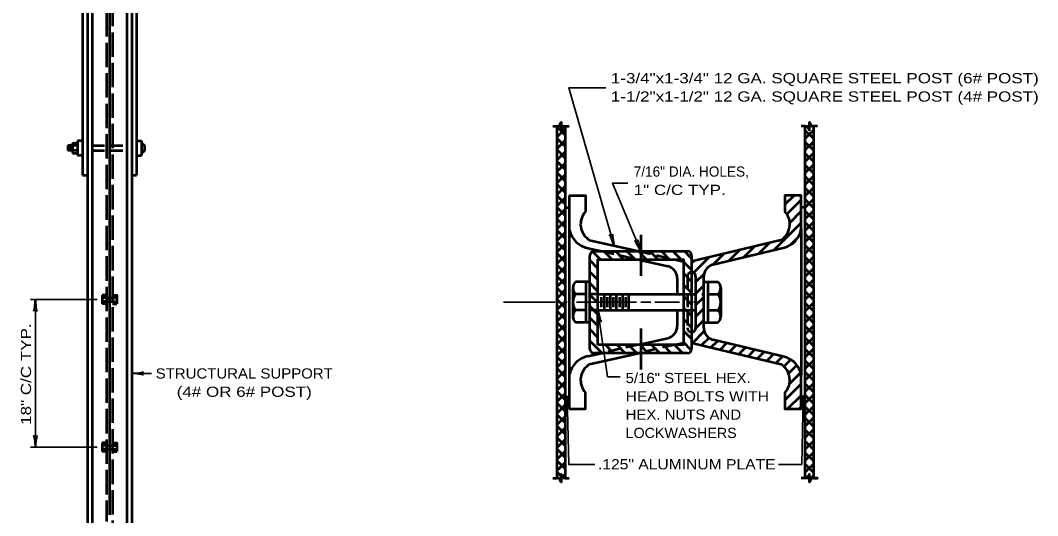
# Model space of a CAD drawing. Extents: x -54 to 626, y -369 to 71.
# Drawn here: x 180.3 to 430.3, y -222.5 to -100.7 of the extents above; entities that cross this region are included whole.
import ezdxf
from ezdxf.enums import TextEntityAlignment as Align

# ---------------------------------------------------------------- set-up
doc = ezdxf.new("R2010")
doc.units = 0
doc.linetypes.add('LONG_DASHED', pattern=[7.5, 6, -1.5])
doc.linetypes.add('MEDIUM_DASHED', pattern=[4.5, 3, -1.5])
doc.layers.add('1', color=7, linetype='Continuous', lineweight=53)

msp = doc.modelspace()

# ---------------------------------------------------------------- linework, layer by layer
at = {"layer": '1'}
for p, q in [((197.973, -26.265), (197.973, -228.335)), ((202.208, -26.265), (202.208, -222.285)), ((195.553, -28.685), (195.553, -138.795)), ((196.763, -28.685), (196.763, -228.335)), ((206.443, -28.685), (206.443, -228.335)), ((207.653, -28.685), (207.653, -228.335)), ((208.863, -28.685), (208.863, -138.795)), ((311.19, -126.746), (312.19, -126.746)), ((314.19, -128.931), (312.19, -126.931)), ((312.19, -129.378), (314.19, -127.378)), ((314.19, -126.746), (315.19, -126.746)), ((373.19, -126.746), (372.19, -126.746)), ((373.19, -126.917), (373.36, -126.746)), ((374.19, -125.917), (374.246, -125.86)), ((374.425, -126.218), (374.19, -125.982)), ((375.19, -126.982), (374.954, -126.746)), ((376.19, -126.746), (375.19, -126.746)), ((314.19, -131.759), (312.19, -129.759)), ((373.19, -129.745), (375.19, -127.745)), ((375.19, -129.811), (373.19, -127.811)), ((194.343, -131.535), (191.923, -131.535)), ((191.923, -131.535), (191.923, -132.745)), ((192.528, -131.838), (192.528, -132.443)), ((193.133, -130.93), (193.133, -133.35)), ((193.133, -130.93), (194.343, -130.93)), ((195.553, -130.325), (194.343, -130.325)), ((194.343, -130.325), (194.343, -133.955)), ((208.863, -130.325), (210.073, -130.325)), ((210.073, -130.325), (210.073, -133.955)), ((312.19, -132.207), (314.19, -130.207)), ((373.19, -132.573), (375.19, -130.573)), ((375.19, -132.639), (373.19, -130.639)), ((194.343, -132.745), (191.923, -132.745)), ((193.133, -133.35), (194.343, -133.35)), ((195.553, -133.955), (194.343, -133.955)), ((208.863, -133.955), (210.073, -133.955)), ((314.19, -134.588), (312.19, -132.588)), ((312.19, -135.035), (314.19, -133.035)), ((373.19, -135.402), (375.19, -133.402)), ((375.19, -135.467), (373.19, -133.467)), ((314.19, -137.416), (312.19, -135.416)), ((312.19, -137.863), (314.19, -135.863)), ((373.19, -138.23), (375.19, -136.23)), ((375.19, -138.296), (373.19, -136.296)), ((195.553, -138.795), (196.763, -138.795)), ((207.653, -138.795), (208.863, -138.795)), ((314.19, -140.245), (312.19, -138.245)), ((312.19, -140.692), (314.19, -138.692)), ((373.19, -141.059), (375.19, -139.059)), ((375.19, -141.124), (373.19, -139.124)), ((314.19, -143.073), (312.19, -141.073)), ((312.19, -143.52), (314.19, -141.52)), ((373.19, -143.887), (375.19, -141.887)), ((375.19, -143.953), (373.19, -141.953)), ((314.19, -145.901), (312.19, -143.901)), ((312.19, -146.349), (314.19, -144.349)), ((315.19, -143.746), (315.19, -196.246)), ((368.19, -145.99), (370.433, -143.746)), ((368.654, -148.354), (372.19, -144.818)), ((373.19, -146.716), (375.19, -144.716)), ((375.19, -146.781), (373.19, -144.781)), ((314.19, -148.73), (312.19, -146.73)), ((312.19, -149.177), (314.19, -147.177)), ((314.19, -146.746), (315.19, -146.746)), ((373.19, -146.746), (372.19, -146.746)), ((314.19, -151.558), (312.19, -149.558)), ((312.19, -152.006), (314.19, -150.006)), ((369.366, -150.471), (372.19, -147.647)), ((373.19, -149.544), (375.19, -147.544)), ((375.19, -149.61), (373.19, -147.61)), ((314.19, -154.387), (312.19, -152.387)), ((365.445, -157.219), (372.19, -150.475)), ((372.19, -152.045), (372.19, -187.948)), ((373.19, -152.372), (375.19, -150.372)), ((375.19, -152.438), (373.19, -150.438)), ((312.19, -154.834), (314.19, -152.834)), ((320.19, -154.746), (332.247, -157.487)), ((332.746, -153.487), (332.746, -163.487)), ((369.593, -155.9), (371.362, -154.131)), ((373.19, -155.201), (375.19, -153.201)), ((375.19, -155.266), (373.19, -153.266)), ((314.19, -157.215), (312.19, -155.215)), ((312.19, -157.662), (314.19, -155.662)), ((319.746, -156.697), (323.222, -157.487)), ((321.246, -157.487), (344.246, -157.487)), ((325.707, -159.487), (323.707, -157.487)), ((328.535, -159.487), (326.535, -157.487)), ((331.364, -159.487), (329.364, -157.487)), ((334.192, -159.487), (332.192, -157.487)), ((337.021, -159.487), (335.021, -157.487)), ((339.849, -159.487), (337.849, -157.487)), ((342.678, -159.487), (340.678, -157.487)), ((345.246, -159.227), (343.506, -157.487)), ((350.55, -160.776), (368.089, -156.588)), ((354.298, -159.881), (357, -157.18)), ((358.014, -158.994), (360.715, -156.293)), ((361.73, -158.107), (364.431, -155.405)), ((373.19, -158.029), (375.19, -156.029)), ((375.19, -158.095), (373.19, -156.095)), ((314.19, -160.044), (312.19, -158.044)), ((312.19, -160.491), (314.19, -158.491)), ((320.246, -181.506), (320.246, -158.487)), ((322.246, -161.683), (320.246, -159.683)), ((322.879, -159.487), (320.936, -157.544)), ((332.022, -159.487), (339.411, -161.166)), ((341.046, -159.487), (343.246, -159.987)), ((345.246, -158.487), (345.246, -159.987)), ((345.246, -160.448), (345.852, -159.842)), ((345.751, -162.771), (349.568, -158.955)), ((350.582, -160.769), (353.284, -158.067)), ((373.19, -160.858), (375.19, -158.858)), ((375.19, -160.923), (373.19, -158.923)), ((314.19, -162.872), (312.19, -160.872)), ((312.19, -163.319), (314.19, -161.319)), ((322.246, -164.511), (320.246, -162.511)), ((345.246, -162.056), (343.246, -160.056)), ((373.19, -163.686), (375.19, -161.686)), ((375.19, -163.752), (373.19, -161.752)), ((314.19, -165.7), (312.19, -163.7)), ((312.19, -166.148), (314.19, -164.148)), ((320.246, -164.996), (316.746, -164.996)), ((319.246, -164.996), (319.246, -174.996)), ((341.746, -164.091), (341.746, -167.996)), ((345.246, -164.884), (343.246, -162.884)), ((345.246, -162.612), (345.246, -177.381)), ((346.246, -165.105), (348.324, -163.027)), ((346.246, -163.694), (346.246, -176.299)), ((348.246, -176.299), (348.246, -163.694)), ((348.246, -164.996), (351.746, -164.996)), ((349.246, -164.996), (349.246, -174.996)), ((373.19, -166.515), (375.19, -164.515)), ((375.19, -166.58), (373.19, -164.58)), ((314.19, -168.529), (312.19, -166.529)), ((312.19, -168.976), (314.19, -166.976)), ((316.074, -166.502), (316.074, -173.491)), ((322.246, -167.34), (320.246, -165.34)), ((345.246, -167.712), (343.246, -165.712)), ((346.246, -167.933), (348.246, -165.933)), ((352.419, -166.502), (352.419, -173.491)), ((373.19, -169.343), (375.19, -167.343)), ((375.19, -169.409), (373.19, -167.409)), ((200.393, -168.289), (200.393, -170.407)), ((201.451, -168.289), (200.393, -168.289)), ((314.19, -171.357), (312.19, -169.357)), ((312.19, -171.805), (314.19, -169.805)), ((319.246, -167.996), (316.746, -167.996)), ((322.246, -170.168), (320.246, -168.168)), ((322.246, -167.996), (343.246, -167.996)), ((322.996, -168.746), (322.996, -171.246)), ((323.746, -167.996), (323.746, -171.996)), ((324.496, -168.746), (324.496, -171.246)), ((325.246, -167.996), (325.246, -171.996)), ((325.996, -168.746), (325.996, -171.246)), ((326.746, -167.996), (326.746, -171.996)), ((327.496, -168.746), (327.496, -171.246)), ((328.246, -167.996), (328.246, -171.996)), ((328.996, -168.746), (328.996, -171.246)), ((329.746, -167.996), (329.746, -171.996)), ((345.246, -170.541), (343.246, -168.541)), ((346.246, -170.761), (348.246, -168.761)), ((349.246, -167.996), (351.746, -167.996)), ((201.451, -170.407), (200.393, -170.407)), ((202.964, -170.407), (204.023, -170.407)), ((314.19, -174.186), (312.19, -172.186)), ((319.246, -171.996), (316.746, -171.996)), ((322.246, -172.997), (320.246, -170.997)), ((322.246, -171.996), (343.246, -171.996)), ((341.746, -171.996), (341.746, -175.902)), ((345.246, -173.369), (343.246, -171.369)), ((346.246, -173.59), (348.246, -171.59)), ((349.246, -171.996), (351.746, -171.996)), ((373.19, -172.171), (375.19, -170.171)), ((375.19, -172.237), (373.19, -170.237)), ((312.19, -174.633), (314.19, -172.633)), ((314.19, -177.014), (312.19, -175.014)), ((320.246, -174.996), (316.746, -174.996)), ((322.246, -175.825), (320.246, -173.825)), ((345.246, -176.198), (343.246, -174.198)), ((346.229, -176.436), (348.246, -174.418)), ((348.246, -174.996), (351.746, -174.996)), ((373.19, -175), (375.19, -173)), ((375.19, -175.065), (373.19, -173.065)), ((312.19, -177.461), (314.19, -175.461)), ((322.246, -178.654), (320.246, -176.654)), ((332.746, -176.506), (332.746, -186.506)), ((345.246, -179.026), (343.246, -177.026)), ((345.246, -177.418), (345.284, -177.38)), ((345.44, -180.053), (348.38, -177.114)), ((373.19, -177.828), (375.19, -175.828)), ((375.19, -177.894), (373.19, -175.894)), ((314.19, -179.843), (312.19, -177.843)), ((312.19, -180.29), (314.19, -178.29)), ((323.271, -182.506), (320.246, -179.482)), ((332.022, -180.506), (339.411, -178.827)), ((341.046, -180.506), (343.246, -180.006)), ((345.188, -181.796), (343.246, -179.855)), ((345.246, -180.006), (345.246, -181.506)), ((347.724, -180.598), (349.563, -178.758)), ((350.007, -181.143), (351.667, -179.483)), ((368.089, -183.405), (350.55, -179.216)), ((373.19, -180.657), (375.19, -178.657)), ((375.19, -180.722), (373.19, -178.722)), ((314.19, -182.671), (312.19, -180.671)), ((312.19, -183.118), (314.19, -181.118)), ((319.746, -183.296), (323.222, -182.506)), ((320.19, -185.246), (332.246, -182.506)), ((344.246, -182.506), (321.246, -182.506)), ((326.099, -182.506), (324.099, -180.506)), ((328.928, -182.506), (326.928, -180.506)), ((331.756, -182.506), (329.756, -180.506)), ((334.585, -182.506), (332.585, -180.506)), ((337.413, -182.506), (335.413, -180.506)), ((340.241, -182.506), (338.241, -180.506)), ((343.07, -182.506), (341.07, -180.506)), ((352.29, -181.688), (353.95, -180.029)), ((354.573, -182.234), (356.233, -180.574)), ((356.856, -182.779), (358.516, -181.119)), ((359.14, -183.324), (360.8, -181.664)), ((361.423, -183.869), (363.083, -182.209)), ((373.19, -183.485), (375.19, -181.485)), ((375.19, -183.551), (373.19, -181.551)), ((314.19, -185.499), (312.19, -183.499)), ((312.19, -185.947), (314.19, -183.947)), ((363.706, -184.415), (365.366, -182.755)), ((365.989, -184.96), (367.649, -183.3)), ((367.948, -185.829), (369.656, -184.121)), ((373.19, -186.314), (375.19, -184.314)), ((375.19, -186.379), (373.19, -184.379)), ((314.19, -188.328), (312.19, -186.328)), ((312.19, -188.775), (314.19, -186.775)), ((369.079, -187.527), (371.114, -185.492)), ((369.269, -190.165), (372.044, -187.391)), ((373.19, -189.142), (375.19, -187.142)), ((375.19, -189.207), (373.19, -187.207)), ((314.19, -191.156), (312.19, -189.156)), ((312.19, -191.604), (314.19, -189.604)), ((373.19, -191.97), (375.19, -189.97)), ((314.19, -193.985), (312.19, -191.985)), ((312.19, -194.432), (314.19, -192.432)), ((368.19, -194.073), (372.19, -190.073)), ((375.19, -192.036), (373.19, -190.036)), ((314.19, -196.813), (312.19, -194.813)), ((314.19, -193.246), (315.19, -193.246)), ((368.845, -196.246), (372.19, -192.901)), ((373.19, -193.246), (372.19, -193.246)), ((373.19, -194.799), (375.19, -192.799)), ((375.19, -194.864), (373.19, -192.864)), ((312.19, -197.26), (314.19, -195.26)), ((371.673, -196.246), (372.19, -195.73)), ((373.19, -197.627), (375.19, -195.627)), ((375.19, -197.693), (373.19, -195.693)), ((314.19, -199.642), (312.19, -197.642)), ((312.19, -200.089), (314.19, -198.089)), ((373.19, -200.456), (375.19, -198.456)), ((375.19, -200.521), (373.19, -198.521)), ((314.19, -202.47), (312.19, -200.47)), ((312.19, -202.917), (314.19, -200.917)), ((373.19, -203.284), (375.19, -201.284)), ((375.19, -203.35), (373.19, -201.35)), ((200.393, -204.589), (200.393, -206.707)), ((201.451, -204.589), (200.393, -204.589)), ((314.19, -205.298), (312.19, -203.298)), ((312.19, -205.746), (314.19, -203.746)), ((373.19, -206.113), (375.19, -204.113)), ((375.19, -206.178), (373.19, -204.178)), ((201.451, -206.707), (200.393, -206.707)), ((202.964, -206.707), (204.023, -206.707)), ((314.19, -208.127), (312.19, -206.127)), ((312.19, -208.574), (314.19, -206.574)), ((373.19, -208.941), (375.19, -206.941)), ((375.19, -209.006), (373.19, -207.006)), ((314.19, -210.955), (312.19, -208.955)), ((312.19, -211.403), (314.19, -209.403)), ((373.19, -211.769), (375.19, -209.769)), ((375.19, -211.835), (373.19, -209.835)), ((313.19, -212.784), (312.19, -211.784)), ((313.518, -212.903), (314.19, -212.231)), ((311.19, -213.246), (312.19, -213.246)), ((312.851, -213.57), (313.19, -213.231)), ((314.19, -213.246), (315.19, -213.246)), ((373.19, -213.246), (372.19, -213.246)), ((373.773, -213.246), (373.19, -212.663)), ((374.541, -213.246), (375.19, -212.598))]:
    msp.add_line(p, q, dxfattribs=at)
at = {"layer": '1', "linetype": 'LONG_DASHED'}
for p, q in [((202.964, -28.685), (202.964, -228.335)), ((201.451, -46.23), (201.451, -223.926))]:
    msp.add_line(p, q, dxfattribs=at)
at = {"layer": '1', "linetype": 'MEDIUM_DASHED'}
for p, q in [((197.973, -131.535), (206.443, -131.535)), ((197.973, -132.745), (206.443, -132.745)), ((323.222, -157.487), (332.022, -159.487)), ((332.247, -157.487), (341.046, -159.487)), ((344.246, -163.694), (344.246, -176.299)), ((201.451, -168.894), (200.393, -168.894)), ((201.451, -169.802), (200.393, -169.802)), ((201.451, -168.894), (202.964, -168.894)), ((201.451, -168.894), (202.964, -168.894)), ((201.451, -169.802), (202.964, -169.802)), ((202.964, -168.894), (204.023, -168.894)), ((202.964, -169.802), (204.023, -169.802)), ((322.246, -167.996), (320.246, -167.996)), ((343.246, -167.996), (348.246, -167.996)), ((322.246, -171.996), (320.246, -171.996)), ((343.246, -171.996), (348.246, -171.996)), ((332.022, -180.506), (323.222, -182.506)), ((341.046, -180.506), (332.246, -182.506)), ((201.451, -205.194), (200.393, -205.194)), ((201.451, -206.102), (200.393, -206.102)), ((201.451, -205.194), (202.964, -205.194)), ((201.451, -206.102), (202.964, -206.102)), ((202.964, -205.194), (204.023, -205.194)), ((202.964, -206.102), (204.023, -206.102))]:
    msp.add_line(p, q, dxfattribs=at)
at = {"layer": '1', "lineweight": 35}
for p, q in [((199.183, -169.348), (182.771, -169.348)), ((183.981, -169.348), (183.981, -205.648)), ((299.017, -169.996), (311.69, -169.996)), ((313.69, -169.996), (314.69, -169.996)), ((316.984, -169.996), (331.746, -169.996)), ((332.746, -169.996), (335.246, -169.996)), ((336.246, -169.996), (342.246, -169.996)), ((345.71, -169.996), (347.198, -169.996)), ((207.653, -187.498), (212.493, -187.498)), ((314.69, -193.246), (315.059, -209.89)), ((372.69, -193.246), (372.321, -209.89)), ((199.183, -205.648), (182.771, -205.648)), ((315.014, -209.861), (321.49, -209.861)), ((366.651, -209.89), (372.365, -209.89))]:
    msp.add_line(p, q, dxfattribs=at)
for points in [[(326.218, -156.117), (315.102, -117.3), (324.167, -117.3)], [(332.746, -157.487), (325.846, -140.726), (329.606, -140.726)], [(322.246, -171.996), (324.623, -188.341), (327.713, -188.341)]]:
    msp.add_lwpolyline(points, dxfattribs=at)
at = {"layer": '1'}
for points in [[(312.19, -213.246), (312.19, -126.746), (312.69, -126.746), (313.19, -125.746), (313.19, -127.746), (313.69, -126.746), (314.19, -126.746), (314.19, -213.246), (313.69, -213.246), (313.19, -212.246), (313.19, -214.246), (312.69, -213.246)], [(373.19, -213.246), (373.19, -126.746), (373.69, -126.746), (374.19, -127.746), (374.19, -125.746), (374.69, -126.746), (375.19, -126.746), (375.19, -213.246), (376.19, -213.246)], [(373.19, -213.246), (373.19, -126.746), (373.69, -126.746), (374.19, -127.746), (374.19, -125.746), (374.69, -126.746), (375.19, -126.746), (375.19, -213.246), (374.69, -213.246), (374.19, -214.246), (374.19, -212.246), (373.69, -213.246)], [(322.246, -180.506), (322.246, -159.487), (343.246, -159.487), (343.246, -180.506)]]:
    msp.add_lwpolyline(points, close=True, dxfattribs=at)
for points in [[(315.19, -143.746), (319.19, -143.746), (319.19, -147.746)], [(372.19, -152.045), (372.19, -143.746), (368.19, -143.746), (368.19, -147.746)], [(367.19, -154.746), (345.246, -159.987), (345.246, -162.612)], [(202.964, -168.289), (204.023, -168.289), (204.023, -170.407)], [(345.246, -177.381), (345.246, -180.006), (367.19, -185.246)], [(368.19, -192.246), (368.19, -196.246), (372.19, -196.246), (372.19, -187.948)], [(315.19, -196.246), (319.19, -196.246), (319.19, -192.246)], [(202.964, -204.589), (204.023, -204.589), (204.023, -206.707)]]:
    msp.add_lwpolyline(points, dxfattribs=at)
for centre, radius, start, end in [((209.6, -132.14), 1.299, 291.34576, 68.65425), ((322.536, -150.84), 4.557, 137.24693, 239.01328), ((364.844, -150.84), 4.557, 300.98672, 42.75307), ((320.851, -151.057), 5.747, 192.24961, 258.91782), ((366.528, -151.057), 5.747, 285.76159, 350.09896), ((321.246, -158.487), 1, 90, 180), ((344.246, -158.487), 1, 0, 90), ((338.746, -164.091), 3, 0, 77.19552), ((351.246, -163.694), 3, 103.43049, 180), ((318.082, -166.496), 2.008, 131.68177, 180.15453), ((345.238, -163.623), 1.011, 355.93658, 88.42125), ((350.411, -166.496), 2.008, 359.84547, 48.31823), ((318.082, -166.496), 2.008, 180.15453, 228.31823), ((318.082, -166.507), 2.008, 179.84547, 228.31823), ((350.411, -166.496), 2.008, 311.68177, 359.84548), ((350.411, -166.507), 2.008, 311.68177, 0.15452), ((319.383, -169.996), 3.309, 142.81241, 217.18759), ((319.383, -169.996), 3.309, 142.81241, 217.18759), ((349.11, -169.996), 3.309, 322.81241, 37.18759), ((349.11, -169.996), 3.309, 322.81241, 37.18759), ((318.082, -173.486), 2.008, 131.68177, 180.15453), ((318.082, -173.496), 2.008, 131.68177, 179.84548), ((350.411, -173.486), 2.008, 359.84547, 48.31823), ((350.411, -173.496), 2.008, 0.15452, 48.31823), ((318.082, -173.496), 2.008, 179.84547, 228.31823), ((350.411, -173.496), 2.008, 311.68177, 0.15452), ((338.746, -175.902), 3, 282.80434, 0), ((345.238, -176.37), 1.011, 271.57875, 4.06342), ((351.246, -176.299), 3, 180, 256.56931), ((321.246, -181.506), 1, 180, 270), ((344.246, -181.506), 1, 270, 0), ((320.851, -188.936), 5.747, 101.08218, 167.75039), ((366.528, -188.936), 5.747, 9.90104, 74.23791), ((322.536, -189.153), 4.557, 120.98672, 222.75307), ((364.844, -189.153), 4.557, 317.24693, 59.01328)]:
    msp.add_arc(centre, radius, start, end, dxfattribs=at)
at = {"layer": '1', "linetype": 'MEDIUM_DASHED'}
for centre, start, end in [((345.255, -163.623), 91.57875, 184.06342), ((345.255, -176.37), 175.93658, 268.42125)]:
    msp.add_arc(centre, 1.011, start, end, dxfattribs=at)
at = {"layer": '1', "lineweight": 40}
for centre, major_axis, ratio, start_param, end_param in [((325.652, -155.144), (0.642, -1.674), 0.122415, 0.8963533, 3.1415927), ((326.113, -154.981), (0.315, -1.737), 0.07063, 3.1407148, 5.41811), ((332.076, -156.583), (0.824, -1.592), 0.122415, 0.8963533, 3.1415927), ((332.516, -156.37), (0.506, -1.691), 0.07063, 3.1407148, 5.41811), ((183.769, -170.468), (0.176, 1.756), 0.07063, 3.1407148, 5.41811), ((183.769, -170.468), (0.176, 1.756), 0.07063, 3.1407148, 5.41811), ((184.257, -170.439), (-0.156, 1.786), 0.122415, 0.8963533, 3.1415927), ((184.257, -170.439), (-0.156, 1.786), 0.122415, 0.8963533, 3.1415927), ((322.198, -173.136), (-0.079, 1.763), 0.07063, 3.1407148, 5.41811), ((322.677, -173.037), (-0.411, 1.745), 0.122415, 0.8963533, 3.1415927), ((208.773, -187.709), (-1.756, 0.176), 0.07063, 3.1407148, 5.41811), ((208.744, -187.222), (-1.786, -0.156), 0.122415, 0.8963533, 3.1415927), ((314.503, -194.371), (0.137, 1.76), 0.07063, 3.1407148, 5.41811), ((314.99, -194.331), (-0.196, 1.782), 0.122415, 0.8963533, 3.1415927), ((372.453, -194.362), (0.215, 1.752), 0.07063, 3.1407148, 5.41811), ((372.942, -194.344), (-0.117, 1.789), 0.122415, 0.8963533, 3.1415927), ((183.705, -204.557), (0.156, -1.786), 0.122415, 0.8963533, 3.1415927), ((183.705, -204.557), (0.156, -1.786), 0.122415, 0.8963533, 3.1415927), ((184.193, -204.527), (-0.176, -1.756), 0.07063, 3.1407148, 5.41811), ((184.193, -204.527), (-0.176, -1.756), 0.07063, 3.1407148, 5.41811)]:
    msp.add_ellipse(centre, major_axis=major_axis, ratio=ratio, start_param=start_param, end_param=end_param, dxfattribs=at)

# ---------------------------------------------------------------- texts
at = {"layer": '1'}
for s, width, p in [('1-3/4"x1-3/4" 12 GA. SQUARE STEEL POST (6# POST)', 1.25, (325.409, -116.207)), ('1-1/2"x1-1/2" 12 GA. SQUARE STEEL POST (4# POST)', 1.25, (325.409, -120.707)), ('1" C/C TYP.', 1.25, (331.025, -143.646)), ('5/16" STEEL HEX.', 1.1, (329.03, -189.875)), ('HEAD BOLTS WITH', 1.15, (329.03, -194.375)), ('HEX. NUTS AND', 1.1, (329.03, -198.875)), ('LOCKWASHERS', 1.05, (329.03, -203.375))]:
    msp.add_text(s, height=2.5, dxfattribs=dict(at, width=width)).set_placement(p)
msp.add_text('7/16" DIA. HOLES,', height=2.5, dxfattribs=at).set_placement((331.025, -139.146))
at = {"layer": '1', "width": 1.25}
msp.add_text('18" C/C TYP.', height=2.5, rotation=90, dxfattribs=at).set_placement((182.914, -187.679), align=Align.CENTER)
at = {"layer": '1'}
for s, width, p in [('STRUCTURAL SUPPORT', 1.1, (235.307, -188.759)), ('(4# OR 6# POST)', 1.25, (235.306, -193.259)), ('.125" ALUMINUM PLATE', 1.15, (344.071, -211.073))]:
    msp.add_text(s, height=2.5, dxfattribs=dict(at, width=width)).set_placement(p, align=Align.CENTER)

doc.saveas('drawing.dxf')
